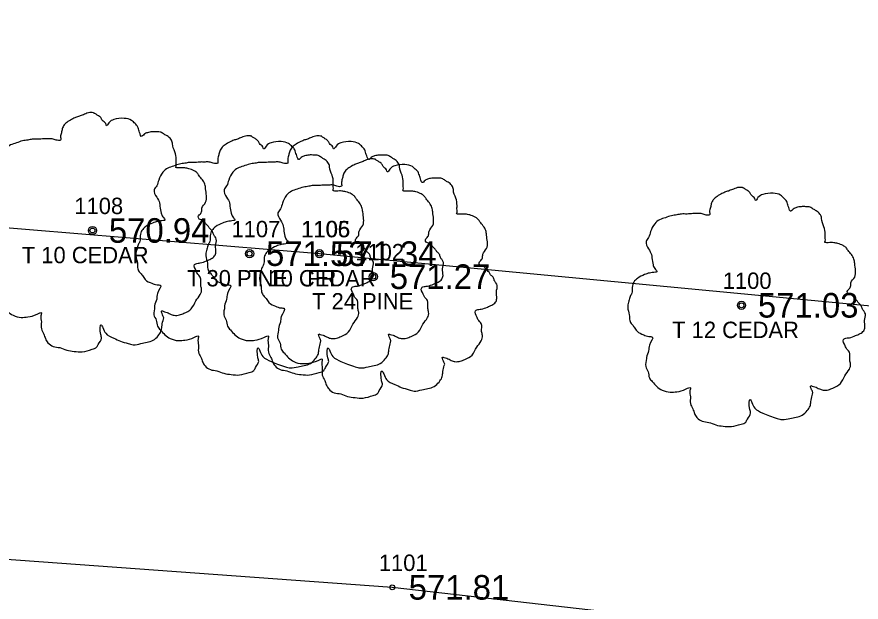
# Model space of a CAD drawing. Extents: x 1529475 to 1532053, y 876698 to 877911.
# Drawn here: x 1531214.4 to 1531265.9, y 877286.3 to 877322 of the extents above; entities that cross this region are included whole.
import ezdxf

# ---------------------------------------------------------------- set-up
doc = ezdxf.new("R2010")
doc.units = 0
for name, color, linetype in [('RD_EX_Fence_Other', 7, 'Continuous'), ('RD_EX_Fence_Other_txCode', 7, 'Continuous'), ('RD_EX_Road', 7, 'Continuous'), ('RD_EX_Road_txCode', 7, 'Continuous'), ('RD_EX_TX_Fence_Other_ELEV', 7, 'Continuous'), ('RD_EX_TX_Road_ELEV', 7, 'Continuous'), ('RD_EX_TX_VEG_ELEV', 7, 'Continuous'), ('RD_EX_VEG', 7, 'Continuous'), ('RD_EX_VEG_txCode', 7, 'Continuous'), ('RD_SMD_Locator', 7, 'Continuous')]:
    doc.layers.add(name, color=color, linetype=linetype)

msp = doc.modelspace()

# ---------------------------------------------------------------- linework, layer by layer
at = {"layer": 'RD_EX_Fence_Other'}
msp.add_lwpolyline([(1531287.683, 877345.243), (1531281.932, 877317.977), (1531278.086, 877303.259), (1531232.889, 877307.565), (1531185.71, 877311.458), (1531137.538, 877312.532), (1531141.511, 877357.73)], dxfattribs=at)
at = {"layer": 'RD_EX_Road'}
msp.add_lwpolyline([(1531606.641, 877133.837), (1531579.15, 877155.048), (1531564.866, 877165.268), (1531535.216, 877186.029), (1531511.532, 877200.27), (1531474.57, 877218.901), (1531430.451, 877239.347), (1531404.48, 877249.379), (1531382.323, 877256.431), (1531333.233, 877270.709), (1531303.666, 877277.444), (1531276.518, 877282.709), (1531237.324, 877287.202), (1531185.802, 877290.94), (1531132.609, 877292.767), (1531081.114, 877292.384), (1531038.69, 877288.667), (1530976.423, 877285.451), (1530941.057, 877284.256)], dxfattribs=at)
at = {"layer": 'RD_EX_VEG'}
for centre, radius in [((1531219.039, 877308.981), 0.25), ((1531219.026, 877308.962), 0.0001), ((1531228.622, 877307.567), 0.25), ((1531232.889, 877307.565), 0.25), ((1531228.609, 877307.548), 0.0001), ((1531232.877, 877307.546), 0.0001), ((1531236.169, 877306.159), 0.25), ((1531236.157, 877306.14), 0.0001), ((1531258.621, 877304.415), 0.25), ((1531258.608, 877304.397), 0.0001)]:
    msp.add_circle(centre, radius, dxfattribs=at)
for points in [[(1531219.17, 877316.149), (1531218.871, 877316.174), (1531218.546, 877316.074), (1531218.296, 877315.974), (1531218.071, 877315.899), (1531217.846, 877315.799), (1531217.546, 877315.624), (1531217.321, 877315.424), (1531217.196, 877315.174), (1531217.146, 877314.949), (1531217.096, 877314.674), (1531217.096, 877314.499), (1531216.971, 877314.474), (1531216.821, 877314.499), (1531216.572, 877314.574), (1531216.322, 877314.574), (1531216.072, 877314.574), (1531215.722, 877314.549), (1531215.372, 877314.549), (1531215.097, 877314.499), (1531214.772, 877314.449), (1531214.398, 877314.324), (1531214.048, 877314.199), (1531213.748, 877313.949), (1531213.498, 877313.475), (1531213.373, 877313.125), (1531213.223, 877312.875), (1531213.373, 877312.425), (1531213.548, 877312.075), (1531213.573, 877311.875), (1531213.648, 877311.451), (1531213.748, 877311.226), (1531213.873, 877311.026), (1531213.798, 877311.001), (1531213.423, 877310.951), (1531213.123, 877310.851), (1531212.698, 877310.626), (1531212.473, 877310.401), (1531212.373, 877310.076), (1531212.348, 877309.726), (1531212.249, 877309.526), (1531212.174, 877309.252), (1531212.149, 877309.177), (1531212.099, 877308.852), (1531212.199, 877308.402), (1531212.224, 877308.052), (1531212.348, 877307.827), (1531212.498, 877307.652), (1531212.673, 877307.402), (1531213.073, 877307.177), (1531213.398, 877307.077), (1531213.598, 877307.053), (1531213.423, 877306.553), (1531213.373, 877306.203), (1531213.248, 877305.803), (1531213.248, 877305.728), (1531213.198, 877305.253), (1531213.348, 877304.928), (1531213.423, 877304.554), (1531213.598, 877304.329), (1531213.873, 877304.029), (1531214.198, 877303.804), (1531214.697, 877303.679), (1531215.097, 877303.704), (1531215.672, 877303.879), (1531215.922, 877303.954), (1531215.897, 877303.779), (1531215.922, 877303.404), (1531215.922, 877302.979), (1531216.072, 877302.654), (1531216.172, 877302.38), (1531216.322, 877302.13), (1531216.647, 877301.905), (1531217.046, 877301.83), (1531217.471, 877301.68), (1531217.921, 877301.605), (1531218.421, 877301.58), (1531219.021, 877301.73), (1531219.295, 877301.855), (1531219.395, 877302.03), (1531219.595, 877302.405), (1531219.545, 877302.629), (1531219.57, 877303.229), (1531219.67, 877303.054), (1531219.845, 877302.704), (1531220.345, 877302.405), (1531220.745, 877302.23), (1531221.22, 877302.08), (1531221.519, 877302.005), (1531221.994, 877302.08), (1531222.369, 877302.155), (1531222.744, 877302.28), (1531223.044, 877302.554), (1531223.219, 877302.829), (1531223.269, 877303.104), (1531223.344, 877303.479), (1531223.394, 877303.654)], [(1531223.394, 877303.654), (1531223.319, 877303.829), (1531223.269, 877304.079), (1531223.344, 877304.054), (1531223.519, 877304.004), (1531223.793, 877303.879), (1531224.018, 877303.804), (1531224.343, 877303.829), (1531224.618, 877303.929), (1531225.068, 877304.204), (1531225.343, 877304.679), (1531225.618, 877305.078), (1531225.693, 877305.403), (1531225.643, 877305.628), (1531225.618, 877306.128), (1531225.418, 877306.378), (1531225.368, 877306.503), (1531225.268, 877306.903), (1531225.343, 877306.953), (1531225.618, 877307.003), (1531225.992, 877307.127), (1531226.267, 877307.252), (1531226.492, 877307.427), (1531226.567, 877307.652), (1531226.542, 877308.052), (1531226.592, 877308.452), (1531226.517, 877308.602), (1531226.417, 877308.752), (1531226.342, 877308.952), (1531226.192, 877309.102), (1531226.092, 877309.252), (1531225.992, 877309.351), (1531225.868, 877309.501), (1531225.693, 877309.626), (1531225.543, 877309.676), (1531225.493, 877309.826), (1531225.643, 877310.026), (1531225.693, 877310.126), (1531225.718, 877310.351), (1531225.943, 877310.701), (1531225.992, 877311.101), (1531225.943, 877311.526), (1531225.893, 877311.8), (1531225.743, 877312.075), (1531225.543, 877312.325), (1531225.418, 877312.5), (1531225.243, 877312.625), (1531224.918, 877312.75), (1531224.668, 877312.8), (1531224.318, 877312.8), (1531224.118, 877312.85), (1531224.143, 877312.9), (1531224.143, 877313.05), (1531224.143, 877313.325), (1531224.068, 877313.775), (1531223.918, 877314.274), (1531223.918, 877314.299), (1531223.818, 877314.549), (1531223.594, 877314.749), (1531223.419, 877314.849), (1531223.219, 877314.974), (1531222.969, 877314.999), (1531222.669, 877314.999), (1531222.394, 877314.949), (1531222.194, 877314.849), (1531222.019, 877314.724), (1531221.944, 877314.874), (1531221.844, 877315.174), (1531221.794, 877315.324), (1531221.644, 877315.499), (1531221.42, 877315.699), (1531220.97, 877315.824), (1531220.345, 877315.749), (1531220.045, 877315.549), (1531219.895, 877315.374), (1531219.845, 877315.499), (1531219.645, 877315.699), (1531219.545, 877315.874), (1531219.37, 877315.999), (1531219.22, 877316.099), (1531219.12, 877316.149)], [(1531228.754, 877314.734), (1531228.454, 877314.759), (1531228.129, 877314.659), (1531227.879, 877314.559), (1531227.654, 877314.484), (1531227.429, 877314.384), (1531227.129, 877314.209), (1531226.905, 877314.009), (1531226.78, 877313.759), (1531226.73, 877313.534), (1531226.68, 877313.259), (1531226.68, 877313.084), (1531226.555, 877313.059), (1531226.405, 877313.084), (1531226.155, 877313.159), (1531225.905, 877313.159), (1531225.655, 877313.159), (1531225.305, 877313.134), (1531224.955, 877313.134), (1531224.681, 877313.084), (1531224.356, 877313.035), (1531223.981, 877312.91), (1531223.631, 877312.785), (1531223.331, 877312.535), (1531223.081, 877312.06), (1531222.956, 877311.71), (1531222.806, 877311.46), (1531222.956, 877311.01), (1531223.131, 877310.661), (1531223.156, 877310.461), (1531223.231, 877310.036), (1531223.331, 877309.811), (1531223.456, 877309.611), (1531223.381, 877309.586), (1531223.006, 877309.536), (1531222.706, 877309.436), (1531222.282, 877309.211), (1531222.057, 877308.986), (1531221.957, 877308.661), (1531221.932, 877308.312), (1531221.832, 877308.112), (1531221.757, 877307.837), (1531221.732, 877307.762), (1531221.682, 877307.437), (1531221.782, 877306.987), (1531221.807, 877306.637), (1531221.932, 877306.412), (1531222.082, 877306.238), (1531222.257, 877305.988), (1531222.656, 877305.763), (1531222.981, 877305.663), (1531223.181, 877305.638), (1531223.006, 877305.138), (1531222.956, 877304.788), (1531222.831, 877304.388), (1531222.831, 877304.313), (1531222.781, 877303.839), (1531222.931, 877303.514), (1531223.006, 877303.139), (1531223.181, 877302.914), (1531223.456, 877302.614), (1531223.781, 877302.389), (1531224.281, 877302.264), (1531224.681, 877302.289), (1531225.255, 877302.464), (1531225.505, 877302.539), (1531225.48, 877302.364), (1531225.505, 877301.989), (1531225.505, 877301.565), (1531225.655, 877301.24), (1531225.755, 877300.965), (1531225.905, 877300.715), (1531226.23, 877300.49), (1531226.63, 877300.415), (1531227.054, 877300.265), (1531227.504, 877300.19), (1531228.004, 877300.165), (1531228.604, 877300.315), (1531228.879, 877300.44), (1531228.979, 877300.615), (1531229.179, 877300.99), (1531229.129, 877301.215), (1531229.154, 877301.814), (1531229.253, 877301.639), (1531229.428, 877301.29), (1531229.928, 877300.99), (1531230.328, 877300.815), (1531230.803, 877300.665), (1531231.103, 877300.59), (1531231.577, 877300.665), (1531231.952, 877300.74), (1531232.327, 877300.865), (1531232.627, 877301.14), (1531232.802, 877301.415), (1531232.852, 877301.689), (1531232.927, 877302.064), (1531232.977, 877302.239)], [(1531233.021, 877314.733), (1531232.721, 877314.758), (1531232.396, 877314.658), (1531232.147, 877314.558), (1531231.922, 877314.483), (1531231.697, 877314.383), (1531231.397, 877314.208), (1531231.172, 877314.008), (1531231.047, 877313.758), (1531230.997, 877313.533), (1531230.947, 877313.258), (1531230.947, 877313.083), (1531230.822, 877313.058), (1531230.672, 877313.083), (1531230.422, 877313.158), (1531230.172, 877313.158), (1531229.922, 877313.158), (1531229.573, 877313.133), (1531229.223, 877313.133), (1531228.948, 877313.083), (1531228.623, 877313.033), (1531228.248, 877312.908), (1531227.898, 877312.783), (1531227.599, 877312.533), (1531227.349, 877312.059), (1531227.224, 877311.709), (1531227.074, 877311.459), (1531227.224, 877311.009), (1531227.399, 877310.659), (1531227.424, 877310.459), (1531227.499, 877310.035), (1531227.599, 877309.81), (1531227.723, 877309.61), (1531227.649, 877309.585), (1531227.274, 877309.535), (1531226.974, 877309.435), (1531226.549, 877309.21), (1531226.324, 877308.985), (1531226.224, 877308.66), (1531226.199, 877308.31), (1531226.099, 877308.11), (1531226.024, 877307.836), (1531225.999, 877307.761), (1531225.949, 877307.436), (1531226.049, 877306.986), (1531226.074, 877306.636), (1531226.199, 877306.411), (1531226.349, 877306.236), (1531226.524, 877305.986), (1531226.924, 877305.761), (1531227.249, 877305.661), (1531227.449, 877305.637), (1531227.274, 877305.137), (1531227.224, 877304.787), (1531227.099, 877304.387), (1531227.099, 877304.312), (1531227.049, 877303.837), (1531227.199, 877303.512), (1531227.274, 877303.138), (1531227.449, 877302.913), (1531227.723, 877302.613), (1531228.048, 877302.388), (1531228.548, 877302.263), (1531228.948, 877302.288), (1531229.523, 877302.463), (1531229.773, 877302.538), (1531229.748, 877302.363), (1531229.773, 877301.988), (1531229.773, 877301.563), (1531229.922, 877301.238), (1531230.022, 877300.964), (1531230.172, 877300.714), (1531230.497, 877300.489), (1531230.897, 877300.414), (1531231.322, 877300.264), (1531231.772, 877300.189), (1531232.271, 877300.164), (1531232.871, 877300.314), (1531233.146, 877300.439), (1531233.246, 877300.614), (1531233.446, 877300.989), (1531233.396, 877301.213), (1531233.421, 877301.813), (1531233.521, 877301.638), (1531233.696, 877301.288), (1531234.196, 877300.989), (1531234.595, 877300.814), (1531235.07, 877300.664), (1531235.37, 877300.589), (1531235.845, 877300.664), (1531236.22, 877300.739), (1531236.595, 877300.864), (1531236.894, 877301.138), (1531237.069, 877301.413), (1531237.119, 877301.688), (1531237.194, 877302.063), (1531237.244, 877302.238)], [(1531232.977, 877302.239), (1531232.902, 877302.414), (1531232.852, 877302.664), (1531232.927, 877302.639), (1531233.102, 877302.589), (1531233.377, 877302.464), (1531233.602, 877302.389), (1531233.926, 877302.414), (1531234.201, 877302.514), (1531234.651, 877302.789), (1531234.926, 877303.264), (1531235.201, 877303.664), (1531235.276, 877303.988), (1531235.226, 877304.213), (1531235.201, 877304.713), (1531235.001, 877304.963), (1531234.951, 877305.088), (1531234.851, 877305.488), (1531234.926, 877305.538), (1531235.201, 877305.588), (1531235.576, 877305.713), (1531235.851, 877305.838), (1531236.076, 877306.013), (1531236.15, 877306.238), (1531236.126, 877306.637), (1531236.175, 877307.037), (1531236.101, 877307.187), (1531236.001, 877307.337), (1531235.926, 877307.537), (1531235.776, 877307.687), (1531235.676, 877307.837), (1531235.576, 877307.937), (1531235.451, 877308.087), (1531235.276, 877308.212), (1531235.126, 877308.262), (1531235.076, 877308.412), (1531235.226, 877308.611), (1531235.276, 877308.711), (1531235.301, 877308.936), (1531235.526, 877309.286), (1531235.576, 877309.686), (1531235.526, 877310.111), (1531235.476, 877310.386), (1531235.326, 877310.661), (1531235.126, 877310.91), (1531235.001, 877311.085), (1531234.826, 877311.21), (1531234.501, 877311.335), (1531234.251, 877311.385), (1531233.901, 877311.385), (1531233.702, 877311.435), (1531233.727, 877311.485), (1531233.727, 877311.635), (1531233.727, 877311.91), (1531233.652, 877312.36), (1531233.502, 877312.86), (1531233.502, 877312.885), (1531233.402, 877313.134), (1531233.177, 877313.334), (1531233.002, 877313.434), (1531232.802, 877313.559), (1531232.552, 877313.584), (1531232.252, 877313.584), (1531231.977, 877313.534), (1531231.777, 877313.434), (1531231.602, 877313.309), (1531231.527, 877313.459), (1531231.428, 877313.759), (1531231.378, 877313.909), (1531231.228, 877314.084), (1531231.003, 877314.284), (1531230.553, 877314.409), (1531229.928, 877314.334), (1531229.628, 877314.134), (1531229.478, 877313.959), (1531229.428, 877314.084), (1531229.228, 877314.284), (1531229.129, 877314.459), (1531228.954, 877314.584), (1531228.804, 877314.684), (1531228.704, 877314.734)], [(1531237.244, 877302.238), (1531237.169, 877302.413), (1531237.119, 877302.663), (1531237.194, 877302.638), (1531237.369, 877302.588), (1531237.644, 877302.463), (1531237.869, 877302.388), (1531238.194, 877302.413), (1531238.469, 877302.513), (1531238.919, 877302.788), (1531239.193, 877303.263), (1531239.468, 877303.662), (1531239.543, 877303.987), (1531239.493, 877304.212), (1531239.468, 877304.712), (1531239.268, 877304.962), (1531239.218, 877305.087), (1531239.118, 877305.487), (1531239.193, 877305.537), (1531239.468, 877305.587), (1531239.843, 877305.711), (1531240.118, 877305.836), (1531240.343, 877306.011), (1531240.418, 877306.236), (1531240.393, 877306.636), (1531240.443, 877307.036), (1531240.368, 877307.186), (1531240.268, 877307.336), (1531240.193, 877307.536), (1531240.043, 877307.686), (1531239.943, 877307.836), (1531239.843, 877307.935), (1531239.718, 877308.085), (1531239.543, 877308.21), (1531239.393, 877308.26), (1531239.343, 877308.41), (1531239.493, 877308.61), (1531239.543, 877308.71), (1531239.568, 877308.935), (1531239.793, 877309.285), (1531239.843, 877309.685), (1531239.793, 877310.11), (1531239.743, 877310.384), (1531239.593, 877310.659), (1531239.393, 877310.909), (1531239.268, 877311.084), (1531239.093, 877311.209), (1531238.769, 877311.334), (1531238.519, 877311.384), (1531238.169, 877311.384), (1531237.969, 877311.434), (1531237.994, 877311.484), (1531237.994, 877311.634), (1531237.994, 877311.909), (1531237.919, 877312.359), (1531237.769, 877312.858), (1531237.769, 877312.883), (1531237.669, 877313.133), (1531237.444, 877313.333), (1531237.269, 877313.433), (1531237.069, 877313.558), (1531236.819, 877313.583), (1531236.52, 877313.583), (1531236.245, 877313.533), (1531236.045, 877313.433), (1531235.87, 877313.308), (1531235.795, 877313.458), (1531235.695, 877313.758), (1531235.645, 877313.908), (1531235.495, 877314.083), (1531235.27, 877314.283), (1531234.82, 877314.408), (1531234.196, 877314.333), (1531233.896, 877314.133), (1531233.746, 877313.958), (1531233.696, 877314.083), (1531233.496, 877314.283), (1531233.396, 877314.458), (1531233.221, 877314.583), (1531233.071, 877314.683), (1531232.971, 877314.733)], [(1531236.301, 877313.326), (1531236.001, 877313.351), (1531235.676, 877313.251), (1531235.426, 877313.151), (1531235.202, 877313.076), (1531234.977, 877312.976), (1531234.677, 877312.801), (1531234.452, 877312.601), (1531234.327, 877312.351), (1531234.277, 877312.127), (1531234.227, 877311.852), (1531234.227, 877311.677), (1531234.102, 877311.652), (1531233.952, 877311.677), (1531233.702, 877311.752), (1531233.452, 877311.752), (1531233.202, 877311.752), (1531232.853, 877311.727), (1531232.503, 877311.727), (1531232.228, 877311.677), (1531231.903, 877311.627), (1531231.528, 877311.502), (1531231.178, 877311.377), (1531230.878, 877311.127), (1531230.629, 877310.652), (1531230.504, 877310.302), (1531230.354, 877310.052), (1531230.504, 877309.603), (1531230.679, 877309.253), (1531230.703, 877309.053), (1531230.778, 877308.628), (1531230.878, 877308.403), (1531231.003, 877308.203), (1531230.928, 877308.178), (1531230.554, 877308.128), (1531230.254, 877308.028), (1531229.829, 877307.803), (1531229.604, 877307.579), (1531229.504, 877307.254), (1531229.479, 877306.904), (1531229.379, 877306.704), (1531229.304, 877306.429), (1531229.279, 877306.354), (1531229.229, 877306.029), (1531229.329, 877305.579), (1531229.354, 877305.23), (1531229.479, 877305.005), (1531229.629, 877304.83), (1531229.804, 877304.58), (1531230.204, 877304.355), (1531230.529, 877304.255), (1531230.728, 877304.23), (1531230.554, 877303.73), (1531230.504, 877303.38), (1531230.379, 877302.981), (1531230.379, 877302.906), (1531230.329, 877302.431), (1531230.479, 877302.106), (1531230.554, 877301.731), (1531230.728, 877301.506), (1531231.003, 877301.206), (1531231.328, 877300.981), (1531231.828, 877300.856), (1531232.228, 877300.881), (1531232.803, 877301.056), (1531233.052, 877301.131), (1531233.027, 877300.956), (1531233.052, 877300.582), (1531233.052, 877300.157), (1531233.202, 877299.832), (1531233.302, 877299.557), (1531233.452, 877299.307), (1531233.777, 877299.082), (1531234.177, 877299.007), (1531234.602, 877298.857), (1531235.052, 877298.782), (1531235.551, 877298.757), (1531236.151, 877298.907), (1531236.426, 877299.032), (1531236.526, 877299.207), (1531236.726, 877299.582), (1531236.676, 877299.807), (1531236.701, 877300.407), (1531236.801, 877300.232), (1531236.976, 877299.882), (1531237.476, 877299.582), (1531237.875, 877299.407), (1531238.35, 877299.257), (1531238.65, 877299.182), (1531239.125, 877299.257), (1531239.5, 877299.332), (1531239.874, 877299.457), (1531240.174, 877299.732), (1531240.349, 877300.007), (1531240.399, 877300.282), (1531240.474, 877300.657), (1531240.524, 877300.831)], [(1531240.524, 877300.831), (1531240.449, 877301.006), (1531240.399, 877301.256), (1531240.474, 877301.231), (1531240.649, 877301.181), (1531240.924, 877301.056), (1531241.149, 877300.981), (1531241.474, 877301.006), (1531241.749, 877301.106), (1531242.198, 877301.381), (1531242.473, 877301.856), (1531242.748, 877302.256), (1531242.823, 877302.581), (1531242.773, 877302.806), (1531242.748, 877303.305), (1531242.548, 877303.555), (1531242.498, 877303.68), (1531242.398, 877304.08), (1531242.473, 877304.13), (1531242.748, 877304.18), (1531243.123, 877304.305), (1531243.398, 877304.43), (1531243.623, 877304.605), (1531243.698, 877304.83), (1531243.673, 877305.23), (1531243.723, 877305.629), (1531243.648, 877305.779), (1531243.548, 877305.929), (1531243.473, 877306.129), (1531243.323, 877306.279), (1531243.223, 877306.429), (1531243.123, 877306.529), (1531242.998, 877306.679), (1531242.823, 877306.804), (1531242.673, 877306.854), (1531242.623, 877307.004), (1531242.773, 877307.204), (1531242.823, 877307.304), (1531242.848, 877307.529), (1531243.073, 877307.878), (1531243.123, 877308.278), (1531243.073, 877308.703), (1531243.023, 877308.978), (1531242.873, 877309.253), (1531242.673, 877309.503), (1531242.548, 877309.678), (1531242.373, 877309.803), (1531242.049, 877309.928), (1531241.799, 877309.977), (1531241.449, 877309.977), (1531241.249, 877310.027), (1531241.274, 877310.077), (1531241.274, 877310.227), (1531241.274, 877310.502), (1531241.199, 877310.952), (1531241.049, 877311.452), (1531241.049, 877311.477), (1531240.949, 877311.727), (1531240.724, 877311.927), (1531240.549, 877312.027), (1531240.349, 877312.152), (1531240.099, 877312.177), (1531239.8, 877312.177), (1531239.525, 877312.127), (1531239.325, 877312.027), (1531239.15, 877311.902), (1531239.075, 877312.052), (1531238.975, 877312.351), (1531238.925, 877312.501), (1531238.775, 877312.676), (1531238.55, 877312.876), (1531238.1, 877313.001), (1531237.476, 877312.926), (1531237.176, 877312.726), (1531237.026, 877312.551), (1531236.976, 877312.676), (1531236.776, 877312.876), (1531236.676, 877313.051), (1531236.501, 877313.176), (1531236.351, 877313.276), (1531236.251, 877313.326)], [(1531258.753, 877311.583), (1531258.453, 877311.608), (1531258.128, 877311.508), (1531257.878, 877311.408), (1531257.653, 877311.333), (1531257.429, 877311.233), (1531257.129, 877311.058), (1531256.904, 877310.858), (1531256.779, 877310.608), (1531256.729, 877310.383), (1531256.679, 877310.108), (1531256.679, 877309.933), (1531256.554, 877309.908), (1531256.404, 877309.933), (1531256.154, 877310.008), (1531255.904, 877310.008), (1531255.654, 877310.008), (1531255.304, 877309.983), (1531254.955, 877309.983), (1531254.68, 877309.933), (1531254.355, 877309.883), (1531253.98, 877309.758), (1531253.63, 877309.633), (1531253.33, 877309.384), (1531253.08, 877308.909), (1531252.955, 877308.559), (1531252.806, 877308.309), (1531252.955, 877307.859), (1531253.13, 877307.509), (1531253.155, 877307.309), (1531253.23, 877306.885), (1531253.33, 877306.66), (1531253.455, 877306.46), (1531253.38, 877306.435), (1531253.005, 877306.385), (1531252.706, 877306.285), (1531252.281, 877306.06), (1531252.056, 877305.835), (1531251.956, 877305.51), (1531251.931, 877305.16), (1531251.831, 877304.961), (1531251.756, 877304.686), (1531251.731, 877304.611), (1531251.681, 877304.286), (1531251.781, 877303.836), (1531251.806, 877303.486), (1531251.931, 877303.261), (1531252.081, 877303.086), (1531252.256, 877302.836), (1531252.656, 877302.612), (1531252.98, 877302.512), (1531253.18, 877302.487), (1531253.005, 877301.987), (1531252.955, 877301.637), (1531252.831, 877301.237), (1531252.831, 877301.162), (1531252.781, 877300.687), (1531252.93, 877300.362), (1531253.005, 877299.988), (1531253.18, 877299.763), (1531253.455, 877299.463), (1531253.78, 877299.238), (1531254.28, 877299.113), (1531254.68, 877299.138), (1531255.255, 877299.313), (1531255.504, 877299.388), (1531255.479, 877299.213), (1531255.504, 877298.838), (1531255.504, 877298.413), (1531255.654, 877298.089), (1531255.754, 877297.814), (1531255.904, 877297.564), (1531256.229, 877297.339), (1531256.629, 877297.264), (1531257.054, 877297.114), (1531257.504, 877297.039), (1531258.003, 877297.014), (1531258.603, 877297.164), (1531258.878, 877297.289), (1531258.978, 877297.464), (1531259.178, 877297.839), (1531259.128, 877298.064), (1531259.153, 877298.663), (1531259.253, 877298.488), (1531259.428, 877298.138), (1531259.927, 877297.839), (1531260.327, 877297.664), (1531260.802, 877297.514), (1531261.102, 877297.439), (1531261.577, 877297.514), (1531261.952, 877297.589), (1531262.326, 877297.714), (1531262.626, 877297.989), (1531262.801, 877298.263), (1531262.851, 877298.538), (1531262.926, 877298.913), (1531262.976, 877299.088)], [(1531262.976, 877299.088), (1531262.901, 877299.263), (1531262.851, 877299.513), (1531262.926, 877299.488), (1531263.101, 877299.438), (1531263.376, 877299.313), (1531263.601, 877299.238), (1531263.926, 877299.263), (1531264.201, 877299.363), (1531264.65, 877299.638), (1531264.925, 877300.113), (1531265.2, 877300.512), (1531265.275, 877300.837), (1531265.225, 877301.062), (1531265.2, 877301.562), (1531265, 877301.812), (1531264.95, 877301.937), (1531264.85, 877302.337), (1531264.925, 877302.387), (1531265.2, 877302.437), (1531265.575, 877302.562), (1531265.85, 877302.686), (1531266.075, 877302.861), (1531266.15, 877303.086), (1531266.125, 877303.486), (1531266.175, 877303.886), (1531266.1, 877304.036), (1531266, 877304.186), (1531265.925, 877304.386), (1531265.775, 877304.536), (1531265.675, 877304.686), (1531265.575, 877304.786), (1531265.45, 877304.936), (1531265.275, 877305.06), (1531265.125, 877305.11), (1531265.075, 877305.26), (1531265.225, 877305.46), (1531265.275, 877305.56), (1531265.3, 877305.785), (1531265.525, 877306.135), (1531265.575, 877306.535), (1531265.525, 877306.96), (1531265.475, 877307.235), (1531265.325, 877307.509), (1531265.125, 877307.759), (1531265, 877307.934), (1531264.825, 877308.059), (1531264.5, 877308.184), (1531264.251, 877308.234), (1531263.901, 877308.234), (1531263.701, 877308.284), (1531263.726, 877308.334), (1531263.726, 877308.484), (1531263.726, 877308.759), (1531263.651, 877309.209), (1531263.501, 877309.708), (1531263.501, 877309.733), (1531263.401, 877309.983), (1531263.176, 877310.183), (1531263.001, 877310.283), (1531262.801, 877310.408), (1531262.551, 877310.433), (1531262.251, 877310.433), (1531261.977, 877310.383), (1531261.777, 877310.283), (1531261.602, 877310.158), (1531261.527, 877310.308), (1531261.427, 877310.608), (1531261.377, 877310.758), (1531261.227, 877310.933), (1531261.002, 877311.133), (1531260.552, 877311.258), (1531259.927, 877311.183), (1531259.628, 877310.983), (1531259.478, 877310.808), (1531259.428, 877310.933), (1531259.228, 877311.133), (1531259.128, 877311.308), (1531258.953, 877311.433), (1531258.803, 877311.533), (1531258.703, 877311.583)]]:
    msp.add_spline(points, degree=3, dxfattribs=at)
at = {"layer": 'RD_SMD_Locator'}
for centre in [(1531219.039, 877308.981), (1531228.622, 877307.567), (1531232.889, 877307.565), (1531232.889, 877307.565), (1531236.169, 877306.159), (1531258.621, 877304.415), (1531237.324, 877287.202)]:
    msp.add_circle(centre, 0.15, dxfattribs=at)

# ---------------------------------------------------------------- texts
at = {"layer": 'RD_EX_Fence_Other_txCode'}
for s, p in [('1106', (1531231.763, 877308.565)), ('FR', (1531232.133, 877305.565))]:
    msp.add_text(s, height=1, dxfattribs=at).set_placement(p)
at = {"layer": 'RD_EX_Road_txCode'}
msp.add_text('1101', height=1, dxfattribs=at).set_placement((1531236.505, 877288.202))
at = {"layer": 'RD_EX_TX_Fence_Other_ELEV'}
msp.add_text('571.34', height=1.5, dxfattribs=at).set_placement((1531233.889, 877306.815))
at = {"layer": 'RD_EX_TX_Road_ELEV'}
msp.add_text('571.81', height=1.5, dxfattribs=at).set_placement((1531238.324, 877286.452))
at = {"layer": 'RD_EX_TX_VEG_ELEV'}
for s, p in [('570.94', (1531220.039, 877308.231)), ('571.53', (1531229.622, 877306.817)), ('571.34', (1531233.889, 877306.815)), ('571.27', (1531237.169, 877305.409)), ('571.03', (1531259.621, 877303.665))]:
    msp.add_text(s, height=1.5, dxfattribs=at).set_placement(p)
at = {"layer": 'RD_EX_VEG_txCode'}
for s, p in [('1108', (1531217.936, 877309.981)), ('1107', (1531227.519, 877308.567)), ('1105', (1531231.787, 877308.565)), ('T 10 CEDAR', (1531214.731, 877306.981)), ('1102', (1531235.067, 877307.159)), ('T 30 PINE', (1531224.807, 877305.567)), ('T 10 CEDAR', (1531228.582, 877305.565)), ('1100', (1531257.479, 877305.415)), ('T 24 PINE', (1531232.433, 877304.159)), ('T 12 CEDAR', (1531254.393, 877302.415))]:
    msp.add_text(s, height=1, dxfattribs=at).set_placement(p)

doc.saveas('drawing.dxf')
